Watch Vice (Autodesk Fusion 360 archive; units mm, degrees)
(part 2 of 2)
sketch "Sketch10" plane through (0, 0, -6.85) normal (0, 0, -1) x axis (1, 0, 0)
  curve K1 (-22.3111, 9.6073) -> (-17.5274, -15.6265)
  curve K2 (17.5274, -15.6265) -> (22.3111, 9.6073)
  curve K3 (19.1583, 15.1523) -> (22.3111, 9.6073)
  line L1 (0, 0) -> (-15.2104, 15.1952)
  line L2 (-5, 0) -> (0, 0)
  line L3 (0, 0) -> (-5, 0)
  line L4 (0, 5) -> (0, 0)
  curve K4 (-22.3111, 9.6073) -> (-19.1583, 15.1523)
  curve K5 (19.1583, 15.1523) -> (14.1277, 21.5832)
  curve K6 (-14.1277, 21.5832) -> (-19.1583, 15.1523)
  line L5 (12.1, 21.5832) -> (14.1277, 21.5832)
  line L6 (-14.1277, 21.5832) -> (-12.1, 21.5832)
  curve K7 (10.8585, -21.0162) -> (17.5274, -15.6265)
  curve K8 (-17.5274, -15.6265) -> (-10.8585, -21.0162)
  line L7 (-20.16, -3.95) -> (-19.7081, -3.95)
  line L8 (-20.16, 3.95) -> (-20.16, -3.95)
  line L9 (-19.7081, 3.95) -> (-20.16, 3.95)
  line L10 (-12.1, 21.5832) -> (-12.1, 22.5)
  line L11 (12.1, 22.5) -> (12.1, 21.5832)
  line L12 (-12.1, 21.4183) -> (-12.1, 21.5832)
  line L13 (12.1, 21.4183) -> (12.1, 21.5832)
  line L14 (-12.1, 21.5832) -> (-12.1, 21.4183)
  line L15 (12.1, 21.5832) -> (12.1, 21.4183)
  arc A1 centre (0, 0) radius 20.1 clockwise from (0.8, -20.0841) to (-0.8, -20.0841)
  circle C1 centre (0, 0) radius 21.6
  circle C2 centre (-15.2104, 15.1952) radius 0.625
  arc A2 centre (-14.0183, 18.4859) radius 1.6 clockwise from (-13.0515, 17.211) to (-14.5633, 16.9815)
  arc A3 centre (-15.2104, 15.1952) radius 1.9 clockwise from (-16.9962, 14.5462) to (-14.5633, 16.9815)
  arc A4 centre (-18.5, 13.9997) radius 1.6 clockwise from (-16.9962, 14.5462) to (-17.2241, 13.0342)
  arc A5 centre (14.0183, 18.4859) radius 1.6 clockwise from (14.5633, 16.9815) to (13.0515, 17.211)
  arc A6 centre (15.2104, 15.1952) radius 1.9 clockwise from (14.5633, 16.9815) to (16.9962, 14.5462)
  circle C3 centre (15.2104, 15.1952) radius 0.625
  arc A7 centre (18.5, 13.9997) radius 1.6 clockwise from (17.2241, 13.0342) to (16.9962, 14.5462)
  arc A8 centre (-14.0183, -18.4859) radius 1.6 clockwise from (-14.5633, -16.9815) to (-13.0515, -17.211)
  arc A9 centre (-15.2104, -15.1952) radius 1.9 clockwise from (-14.5633, -16.9815) to (-16.9962, -14.5462)
  arc A10 centre (-18.5, -13.9997) radius 1.6 clockwise from (-17.2241, -13.0342) to (-16.9962, -14.5462)
  circle C4 centre (-15.2104, -15.1952) radius 0.625
  arc A11 centre (15.2104, -15.1952) radius 1.9 clockwise from (16.9962, -14.5462) to (14.5633, -16.9815)
  arc A12 centre (14.0183, -18.4859) radius 1.6 clockwise from (13.0515, -17.211) to (14.5633, -16.9815)
  circle C5 centre (15.2104, -15.1952) radius 0.625
  arc A13 centre (18.5, -13.9997) radius 1.6 clockwise from (16.9962, -14.5462) to (17.2241, -13.0342)
  arc A14 centre (2.1023, -18.9913) radius 1.7 clockwise from (3.612, -19.7728) to (0.8, -20.0841)
  arc A15 centre (-2.1023, -18.9913) radius 1.7 clockwise from (-0.8, -20.0841) to (-3.612, -19.7728)
  circle C6 centre (0, 0) radius 21
  circle C7 centre (0, 0) radius 20.5
  arc A16 centre (0, 0) radius 20.1 clockwise from (-3.612, -19.7728) to (-19.7081, -3.95)
  arc A17 centre (0, 0) radius 20.1 clockwise from (-19.7081, 3.95) to (3.612, -19.7728)
  closed curve K9 centre (-9.882, 22.5)
  closed curve K10 centre (-9.882, -23)
  arc A18 centre (0, -0.5) radius 22.3908 clockwise from (8.6949, -21.1337) to (-8.6949, -21.1337)
  closed curve K11 centre (9.882, -23)
  closed curve K12 centre (9.882, 22.5)
  arc A19 centre (0, 0) radius 22.3908 clockwise from (-8.6949, 20.6337) to (8.6949, 20.6337)
  point P17 (0, 0)
  point P18 (-5, 0)
  point P19 (0, 5)
  point P15 (-15.2104, 15.1952)
  point P16 (0, 0)
  dimension "d108" distance A1 C1 = 1.5
  dimension "d109" diameter C2 = 1.25
  dimension "d110" radius A3 = 1.9
  dimension "d112" radius A2 = 1.6
  dimension "d113" distance P17 P18 = 5
  dimension "d114" distance P17 P19 = 5
  dimension "d120" distance P15 P16 = 21.5
  dimension "d330" = 0.5
  dimension "d331" diameter C6 = 42
extrude "Extrude15" cut sketch "Sketch10" profile of A1 C1 C2 A2 A3 A4 A5 A6 C3 A7 A8 A9 A10 C4 A11 A12 C5 A13 against normal blind 1
extrude "Extrude16" cut sketch "Sketch10" profile of C1 C2 C3 C4 C5 against normal blind 4
sketch "Sketch11" plane through (0, 0, 4.15) normal (0, 0, 1) x axis (-1, 0, 0)
  curve K1 (19.4592, -12.045) -> (0, -22.01)
  curve K2 (0, 22) -> (19.4592, -12.045)
  curve K3 (-19.4592, -12.045) -> (0, 22)
  curve K4 (0, -22.01) -> (-19.4592, -12.045)
  circle C1 centre (0, 0) radius 19
  circle C2 centre (0, 0) radius 20.05
  circle C3 centre (0, 0) radius 20.7
  dimension "d125" diameter C2 = 40.1
  dimension "d423" diameter C3 = 41.4 (= "40 mm + 0.7 * 2 mm")
extrude "Extrude17" cut sketch "Sketch11" profile of C1 C2 against normal blind 1.3
extrude "Extrude37" sketch "Sketch11" profile of C2 C3 blind 0.75 from offset 0.05
extrude "Extrude18" cut of existing geometry no distance stored
work_plane "WorkPlane3"
sketch "Sketch12" plane through (0, 0, -1.75) normal (0, 0, 1) x axis (-1, 0, 0)
  line L1 (-24.1674, 0.75) -> (-20.086, 0.75)
  curve K1 (-24.1674, 0.75) -> (-24.2538, -0.75)
  line L2 (-20.086, -0.75) -> (-24.2538, -0.75)
  line L3 (-22.75, -10) -> (-22.75, 10)
  line L4 (0, 0) -> (-22.75, 0)
  line L5 (-32.75, -10) -> (-22.75, -10)
  line L6 (-32.75, 10) -> (-32.75, -10)
  line L7 (-22.75, 10) -> (-32.75, 10)
  line L8 (-20.8112, 5) -> (-20.8112, -5)
  line L9 (-10.8112, -5) -> (-20.8112, -5)
  line L10 (-10.8112, 5) -> (-10.8112, -5)
  line L11 (-20.8112, 5) -> (-10.8112, 5)
  line L12 (-22.9169, -7.75) -> (-32.75, -7.75)
  line L13 (-22.9169, 7.75) -> (-32.75, 7.75)
  line L14 (-27.8334, -10) -> (-27.8334, -7.75)
  line L15 (-27.8334, 10) -> (-27.8334, 7.75)
  arc A1 centre (0, 0) radius 20.1 clockwise from (-20.086, -0.75) to (-20.086, 0.75)
  arc A2 centre (96.8326, 0) radius 120 clockwise from (-22.75, -10) to (-22.75, 10)
  arc A3 centre (96.8326, 0) radius 117.75 clockwise from (-20.8112, -5) to (-20.8112, 5)
  arc A4 centre (0, 0) radius 20.1 clockwise from (19.7081, -3.95) to (3.612, -19.7728)
  arc A5 centre (0, 0) radius 20.1 clockwise from (-3.612, -19.7728) to (19.7081, 3.95)
  arc A6 centre (0, 0) radius 20.1 clockwise from (-3.612, -19.7728) to (3.612, -19.7728)
  point P10 (-22.75, 0)
  point P11 (0, 0)
  point P7 (-22.75, -10)
  point P8 (-22.75, 10)
  point P12 (-32.75, -10)
  point P14 (-20.8112, -5)
  point P15 (-20.8112, 5)
  point P17 (-10.8112, -5)
  dimension "d129" radius A2 = 120
  dimension "d130" distance P10 P11 = 22.75
  dimension "d131" distance P7 P8 = 20
  dimension "d132" distance P7 P12 = 10
  dimension "d147" distance P14 P15 = 10
  dimension "d148" distance P14 P17 = 10
  dimension "d153" distance A2 A3 = 2.25
  dimension "d232" distance L12 L13 = 15.5 (= "12 mm + 3.5 mm")
extrude "Extrude19" cut sketch "Sketch12" profile of A2 L6 L7 L12 L13 along normal blind 7 and against normal blind 2
fillet "Fillet13" radius 1.6
extrude "Extrude21" cut sketch "Sketch12" profile of A1 L1 L2 A3 L9 L10 L11 blind 2
fillet "Fillet31" radius 1.7
work_plane "WorkPlane4" AlongDistance 23.124
sketch "Sketch13" plane through (23.124, 0, 0) normal (1, 0, 0) x axis (0, 1, 0)
  line L1 (-3.6, -3.05) -> (-3.6, -0.45)
  line L2 (3.6, -3.05) -> (-3.6, -3.05)
  line L3 (3.6, -0.45) -> (3.6, -3.05)
  line L4 (-3.6, -0.45) -> (3.6, -0.45)
  line L5 (0.75, -1.45) -> (-0.75, -1.45)
  line L6 (-0.75, -2.05) -> (-0.75, -1.45)
  line L7 (-0.75, -1.75) -> (-3.6, -1.75)
  line L8 (0.75, -1.45) -> (0.75, -2.05)
  dimension "d138" distance L4 L5 = 1
  dimension "d139" distance L1 L6 = 2.85
  dimension "d140" distance L3 L8 = 2.85 (= "d139")
  dimension "d247" = 6.5
extrude "Extrude20" cut sketch "Sketch13" profile of L1 L2 L3 L4 along normal blind 1 and against normal blind 10
fillet "Fillet14" radius 0.75
delete_face "DeleteFace9"
fillet "Fillet32" radius 0.5
sketch "Sketch26"
  line L1 (-28.6909, 32.7863) -> (28.6626, 32.7863)
  line L2 (-28.6909, -32.2863) -> (-28.6909, 32.7863)
  line L3 (28.6626, -32.2863) -> (-28.6909, -32.2863)
  line L4 (28.6626, 32.7863) -> (28.6626, -32.2863)
  curve K1 (22.3111, -9.6073) -> (24.2921, 5.9411)
  line L5 (24.6626, -7.9065) -> (24.6626, 0.4411)
  curve K2 (-19.5699, 15.0454) -> (-22.3111, -9.6073)
  line L6 (-24.6909, 1.8927) -> (-24.6909, -8.4539)
  point P6 (12.1, 28.7863)
  point P7 (24.2921, 5.9411)
  point P9 (24.6626, 0.4411)
  point P11 (-22.3111, -9.6073)
  point P14 (-24.6909, 1.8927)
  point P15 (12.1, -28.2863)
  dimension "d417" distance L1 P6 = 4
  dimension "d418" distance P7 P9 = 5.5
  dimension "d419" distance L4 L5 = 4
  dimension "d420" distance P11 P14 = 11.5
  dimension "d421" distance L2 L6 = 4
  dimension "d422" distance L3 P15 = 4
component_insert "Component Insert"
mesh "Mesh5"
named bodies: "WatchBlank", "WatchCase", "Lug3", "Lug1", "Lug2", "Lug4"

design "Watch Vice Fixture CAD"
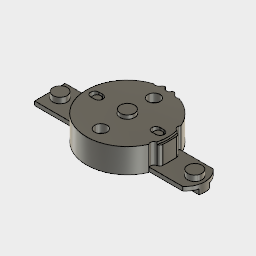
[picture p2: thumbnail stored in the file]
parameter "d90" = 4
parameter "d106" = 4
sketch "Sketch1"
  line L1 (0, 20.2285) -> (0, 20.1)
  line L2 (0, 20.95) -> (0, 20.2285)
  arc A1 centre (0, 0) radius 20.1 clockwise from (19.4682, -5) to (-3.612, 19.7728)
  arc A2 centre (19.1697, -3.3264) radius 1.7 clockwise from (20.869, -3.3751) to (19.4682, -5)
  arc A3 centre (-96.8326, 0) radius 117.75 clockwise from (20.869, 3.3751) to (20.869, -3.3751)
  arc A4 centre (19.1697, 3.3264) radius 1.7 clockwise from (19.4682, 5) to (20.869, 3.3751)
  arc A5 centre (0, 0) radius 20.1 clockwise from (3.612, 19.7728) to (19.4682, 5)
  arc A6 centre (2.1023, 18.9913) radius 1.7 clockwise from (0.8, 20.0841) to (3.612, 19.7728)
  arc A7 centre (0, 0) radius 20.1 clockwise from (-0.8, 20.0841) to (0.8, 20.0841)
  arc A8 centre (-2.1023, 18.9913) radius 1.7 clockwise from (-3.612, 19.7728) to (-0.8, 20.0841)
  arc A9 centre (0, 0) radius 21.6 clockwise from (-17.2241, -13.0342) to (-17.2241, 13.0342)
  arc A10 centre (-18.5, 13.9997) radius 1.6 clockwise from (-16.9962, 14.5462) to (-17.2241, 13.0342)
  arc A11 centre (-15.2104, 15.1952) radius 1.9 clockwise from (-16.9962, 14.5462) to (-14.5633, 16.9815)
  arc A12 centre (-14.0183, 18.4859) radius 1.6 clockwise from (-13.0515, 17.211) to (-14.5633, 16.9815)
  arc A13 centre (0, 0) radius 21.6 clockwise from (-13.0515, 17.211) to (13.0515, 17.211)
  arc A14 centre (14.0183, 18.4859) radius 1.6 clockwise from (14.5633, 16.9815) to (13.0515, 17.211)
  arc A15 centre (15.2104, 15.1952) radius 1.9 clockwise from (14.5633, 16.9815) to (16.9962, 14.5462)
  arc A16 centre (18.5, 13.9997) radius 1.6 clockwise from (17.2241, 13.0342) to (16.9962, 14.5462)
  arc A17 centre (0, 0) radius 21.6 clockwise from (17.2241, 13.0342) to (17.2241, -13.0342)
  arc A18 centre (18.5, -13.9997) radius 1.6 clockwise from (16.9962, -14.5462) to (17.2241, -13.0342)
  arc A19 centre (15.2104, -15.1952) radius 1.9 clockwise from (16.9962, -14.5462) to (14.5633, -16.9815)
  arc A20 centre (14.0183, -18.4859) radius 1.6 clockwise from (13.0515, -17.211) to (14.5633, -16.9815)
  arc A21 centre (0, 0) radius 21.6 clockwise from (13.0515, -17.211) to (-13.0515, -17.211)
  arc A22 centre (-14.0183, -18.4859) radius 1.6 clockwise from (-14.5633, -16.9815) to (-13.0515, -17.211)
  arc A23 centre (-15.2104, -15.1952) radius 1.9 clockwise from (-14.5633, -16.9815) to (-16.9962, -14.5462)
  arc A24 centre (-18.5, -13.9997) radius 1.6 clockwise from (-17.2241, -13.0342) to (-16.9962, -14.5462)
  circle C1 centre (15.2104, 15.1952) radius 0.625
  circle C2 centre (-15.2104, 15.1952) radius 0.625
  circle C3 centre (15.2104, -15.1952) radius 0.625
  circle C4 centre (-15.2104, -15.1952) radius 0.625
  circle C5 centre (5.1662, 20.5772) radius 1.75
  circle C6 centre (-5.1662, 20.5772) radius 1.75
  circle C7 centre (19.7754, 6.7228) radius 1.75
  circle C8 centre (19.7754, -6.7228) radius 1.75
  circle C9 centre (0, 20.1) radius 0.9
  circle C10 centre (0, 20.95) radius 1.75
  arc A25 centre (0, 0) radius 20.1 clockwise from (19.4682, 5) to (19.4682, -5)
  dimension "d6" diameter C8 = 3.5
  dimension "d7" diameter C9 = 1.8
  dimension "d8" diameter C10 = 3.5
extrude "Extrude1" new body sketch "Sketch1" profile of A1 A2 A3 A4 A5 A6 A7 A8 C5 C6 C7 C8 C10 blind 10
extrude "Extrude2" cut sketch "Sketch1" profile of A6 A7 A8 C10 no distance stored
extrude "Extrude3" sketch "Sketch1" profile of A2 A3 A4 A25 blind -1.1
offset_faces "OffsetFaces1" distance -0.1
sketch "Sketch2" plane through (0, 0, 0) normal (1, 0, 0) x axis (0, 1, 0)
  line L1 (-20, 10) -> (19.1, 10)
  line L2 (0, 3) -> (0, 0)
  line L3 (20, 3) -> (-20, 3)
  line L4 (0, 10) -> (0, 3)
  line L5 (-20, 3) -> (-20, 10)
  line L6 (-16, 6) -> (-16, 10)
  line L7 (-14.55, 6) -> (-16, 6)
  line L8 (-14.55, 3) -> (-14.55, 6)
  line L9 (-11.45, 6) -> (-11.45, 3)
  line L10 (-10, 6) -> (-11.45, 6)
  line L11 (-10, 10) -> (-10, 6)
  line L12 (11.45, 6) -> (11.45, 3)
  line L13 (10, 6) -> (11.45, 6)
  line L14 (10, 10) -> (10, 6)
  line L15 (-11.45, 6) -> (-14.55, 6)
  line L16 (-13, 10) -> (-13, 6)
  line L17 (-13, 3) -> (-13, 6)
  line L18 (13, 10) -> (13, 6)
  line L19 (13, 3) -> (13, 6)
  line L20 (-20, 0) -> (19.0241, 0)
  line L21 (-14.25, 0) -> (-14.25, 3)
  line L22 (-13, 0) -> (-13, 3)
  line L23 (-11.75, 0) -> (-11.75, 3)
  line L24 (-11.75, 3) -> (-14.25, 3)
  line L25 (13, 0) -> (13, 3)
  line L26 (11.75, 0) -> (11.75, 3)
  point P10 (-16, 10)
  point P11 (-16, 6)
  point P1 (0, 0)
  dimension "d19" distance P10 P11 = 4
  dimension "d20" distance L8 L9 = 3.1
  dimension "d22" distance L4 L11 = 10
  dimension "d23" distance L6 L11 = 6
  dimension "d24" distance P1 L3 = 3
  dimension "d27" distance L21 L23 = 2.5
  dimension "d28" distance L7 L20 = 6
revolve "Revolve1" sketch "Sketch2" AlongAngle 360
revolve "Revolve2" sketch "Sketch2" AlongAngle 360
work_plane "WorkPlane1" AlongDistance 3
split "Split1" bodies "Clamp Upper"
sketch "Sketch4" plane through (0, 0, 0) normal (0, 1, 0) x axis (1, 0, 0)
  line L1 (-20, 0) -> (20.8174, 0)
  line L2 (20.8174, 4) -> (20.8174, 0)
  line L3 (-20, 4) -> (20.8174, 4)
  line L4 (-20, 0) -> (-20, 4)
  point P4 (20.8174, 0)
  point P5 (20.8174, 4)
  dimension "d41" distance P4 P5 = 4
extrude "Extrude5" add sketch "Sketch4" distance 5.2
delete_face "DeleteFace1"
sketch "Sketch7" plane through (0, 0, 0) normal (0, 0, -1) x axis (1, 0, 0)
  line L1 (20.7887, 2.6) -> (-19.8303, 2.6)
  line L2 (38, 7.5) -> (-38, 7.5)
  line L3 (38, -7.5) -> (38, 7.5)
  line L4 (-38, -7.5) -> (38, -7.5)
  line L5 (-38, 7.5) -> (-38, -7.5)
  line L6 (-19.8303, -2.6) -> (20.7887, -2.6)
  line L7 (-20, 0) -> (-38, 0)
  line L8 (-34.6144, -7.5) -> (-34.6144, 7.5)
  line L9 (0, 7.5) -> (0, 0)
  line L10 (-38, 2.6) -> (-19.8303, 2.6)
  line L11 (-38, -2.6) -> (-19.8303, -2.6)
  line L12 (38, 2.6) -> (20.7887, 2.6)
  line L13 (40.3124, -2.6) -> (20.7887, -2.6)
  arc A1 centre (-96.8326, 0) radius 117.65 clockwise from (20.7691, 3.3723) to (20.7887, 2.6)
  arc A2 centre (19.1697, 3.3264) radius 1.6 clockwise from (19.4506, 4.9016) to (20.7691, 3.3723)
  arc A3 centre (19.7754, 6.7228) radius 1.85 clockwise from (19.4506, 4.9016) to (18.365, 7.92)
  arc A4 centre (0, 0) radius 20 clockwise from (-19.8303, 2.6) to (18.365, 7.92)
  circle C1 centre (0, 13) radius 1.25
  arc A5 centre (0, 0) radius 20 clockwise from (-19.8303, -2.6) to (-19.8303, 2.6)
  circle C2 centre (-33, 0) radius 2.025
  arc A6 centre (-28, 0) radius 10 clockwise from (-34.6144, -7.5) to (-34.6144, 7.5)
  arc A7 centre (28, 0) radius 10 clockwise from (34.6144, 7.5) to (34.6144, -7.5)
  circle C3 centre (33, 0) radius 2.025
  arc A8 centre (5.1662, -20.5772) radius 1.85 clockwise from (3.5232, -19.7268) to (6.1713, -19.0241)
  arc A9 centre (0, 0) radius 20 clockwise from (18.365, -7.92) to (6.1713, -19.0241)
  arc A10 centre (19.7754, -6.7228) radius 1.85 clockwise from (18.365, -7.92) to (19.4506, -4.9016)
  arc A11 centre (19.1697, -3.3264) radius 1.6 clockwise from (20.7691, -3.3723) to (19.4506, -4.9016)
  arc A12 centre (-96.8326, 0) radius 117.65 clockwise from (20.7691, 3.3723) to (20.7691, -3.3723)
  arc A13 centre (19.1697, 3.3264) radius 1.6 clockwise from (19.4506, 4.9016) to (20.7691, 3.3723)
  arc A14 centre (19.7754, 6.7228) radius 1.85 clockwise from (19.4506, 4.9016) to (18.365, 7.92)
  arc A15 centre (0, 0) radius 20 clockwise from (-6.1713, -19.0241) to (18.365, 7.92)
  arc A16 centre (-5.1662, -20.5772) radius 1.85 clockwise from (-6.1713, -19.0241) to (-3.5232, -19.7268)
  arc A17 centre (-2.1023, -18.9913) radius 1.6 clockwise from (-1.8093, -20.5643) to (-3.5232, -19.7268)
  arc A18 centre (0, -20.95) radius 1.85 clockwise from (-1.8093, -20.5643) to (1.8093, -20.5643)
  arc A19 centre (2.1023, -18.9913) radius 1.6 clockwise from (3.5232, -19.7268) to (1.8093, -20.5643)
  circle C4 centre (0, 13) radius 1.55
  circle C5 centre (0, -13) radius 1.55
  point P12 (-38, 7.5)
  point P15 (-38, -7.5)
  point P1 (0, 0)
  point P23 (-33, 0)
  dimension "d73" distance P12 P15 = 15
  dimension "d74" distance P1 P23 = 33
  dimension "d76" radius A6 = 10
  dimension "d77" distance L5 P23 = 5
  dimension "d78" diameter C2 = 4.05
extrude "Extrude14" add sketch "Sketch7" profile of L1 A1 A2 A3 A4 L2 L4 L5 L6 A5 C2 A6 A7 C3 L10 L11 L12 L13 A8 A9 A10 A11 A12 A13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 along normal blind 2
offset_faces "OffsetFaces3" distance 2
extrude "Extrude15" add sketch "Sketch7" profile of L1 L6 A5 C2 A6 A7 C3 L10 L11 L12 L13 A12 A15 along normal blind 4.5
sketch "Sketch3" plane through (0, 0, 0) normal (0, 1, 0) x axis (1, 0, 0)
  line L1 (20, -10) -> (-20, -10)
  line L2 (0, -7) -> (0, 0)
  line L3 (3.6, -9) -> (3.6, -10)
  line L4 (2.1, -9) -> (3.6, -9)
  line L5 (2.1, -7) -> (2.1, -9)
  line L6 (0, -7) -> (2.1, -7)
  line L7 (0, -10) -> (0, -7)
  line L8 (3.6, -10) -> (0, -10)
  line L9 (20.8174, -3) -> (-20, -3)
  line L10 (-22, -7) -> (22, -7)
  line L11 (-22, -1.4022) -> (-22, -7)
  line L12 (22, -1.4022) -> (-22, -1.4022)
  line L13 (22, -7) -> (22, -1.4022)
  point P5 (3.6, -10)
  point P10 (0, -10)
  point P6 (3.6, -9)
  point P7 (2.1, -9)
  point P8 (2.1, -7)
  point P3 (20, -10)
  point P2 (-20, -10)
  dimension "d29" distance L5 L7 = 2.1
  dimension "d30" distance P5 P10 = 3.6
  dimension "d31" distance P5 P6 = 1
  dimension "d32" distance P7 P8 = 2
  dimension "d34" = 1
  dimension "d35" distance P3 L13 = 2
  dimension "d36" distance P2 L11 = 2
revolve "Revolve3" sketch "Sketch3" AlongAngle 360
extrude "Extrude4" cut sketch "Sketch3" profile of L6 L10 L11 L12 L13 distance 10
extrude "Extrude6" new body of existing geometry blind 5.6 bodies "Clamp Jaw 1"
sketch "Sketch5" plane through (0, 0, 0) normal (0, 1, 0) x axis (1, 0, 0)
  line L1 (20.8174, -7.0022) -> (-20, -7.0022)
  line L2 (-20, -1.4022) -> (20.8174, -1.4022)
  line L3 (6.8871, -1.4022) -> (4.8489, -7.0022)
  line L4 (0, -1.4022) -> (0, 0)
  line L5 (0, -7.0022) -> (0, -1.4022)
  line L6 (6.6743, -1.4022) -> (4.636, -7.0022)
  line L7 (0, -6.0022) -> (5, -6.0022)
  line L8 (-6.8871, -1.4022) -> (-4.8489, -7.0022)
  line L9 (-6.6743, -1.4022) -> (-4.636, -7.0022)
  line L10 (0, -6.0022) -> (-5, -6.0022)
  point P13 (5, -6.0022)
  point P14 (0, -6.0022)
  dimension "d47" distance L3 L6 = 0.2
  dimension "d48" angle L2 L6 = 70
  dimension "d49" distance P13 P14 = 5
  dimension "d50" distance L1 L7 = 1
extrude "Extrude7" cut sketch "Sketch5" profile of L1 L2 L3 L5 L6 L7 L8 L9 L10 distance 10 bodies "Clamp Jaw Center", "Clamp Jaws 2"
sketch "Sketch6" plane through (0, 0, 7.0022) normal (0, 0, 1) x axis (-1, 0, 0)
  line L1 (-4.8489, 5) -> (-4.8489, -5)
  line L2 (-19.1013, 5) -> (-4.8489, 5)
  line L3 (-4.8489, -5) -> (-19.1013, -5)
  line L4 (14, -2) -> (16, -2)
  line L5 (16, 2) -> (14, 2)
  line L6 (6.6743, -5) -> (-6.6743, -5)
  line L7 (0, -5) -> (0, 0)
  line L8 (0, 0) -> (14, 0)
  line L9 (16, 0) -> (14, 0)
  line L10 (-14, -2) -> (-16, -2)
  line L11 (-16, 2) -> (-14, 2)
  line L12 (1.7, -4) -> (1.7, -6.1)
  line L13 (-1.7, -4) -> (1.7, -4)
  line L14 (-1.7, -6.1) -> (-1.7, -4)
  line L15 (-1.9, -3.8) -> (1.9, -3.8)
  line L16 (-1.9, -6.1) -> (-1.9, -3.8)
  line L17 (1.9, -3.8) -> (1.9, -6.1)
  line L18 (1.7, 4) -> (1.7, 6.1)
  line L19 (1.9, 3.8) -> (1.9, 6.1)
  line L20 (-1.9, 6.1) -> (-1.9, 3.8)
  line L21 (-1.7, 6.1) -> (-1.7, 4)
  line L22 (-1.7, 4) -> (1.7, 4)
  line L23 (-1.9, 3.8) -> (1.9, 3.8)
  arc A1 centre (-19.1697, 3.3264) radius 1.6 clockwise from (-20.7691, 3.3723) to (-19.4506, 4.9016)
  arc A2 centre (96.8326, 0) radius 117.65 clockwise from (-20.7691, -3.3723) to (-20.7691, 3.3723)
  arc A3 centre (-19.1697, -3.3264) radius 1.6 clockwise from (-19.4506, -4.9016) to (-20.7691, -3.3723)
  arc A4 centre (14, 0) radius 2 clockwise from (14, -2) to (14, 2)
  arc A5 centre (16, 0) radius 2 clockwise from (16, 2) to (16, -2)
  circle C1 centre (15, 0) radius 1.95
  arc A6 centre (-14, 0) radius 2 clockwise from (-14, 2) to (-14, -2)
  arc A7 centre (-16, 0) radius 2 clockwise from (-16, -2) to (-16, 2)
  circle C2 centre (-15, 0) radius 1.95
  circle C3 centre (0, 0) radius 1.75
  arc A8 centre (0, -6.1) radius 1.7 clockwise from (1.7, -6.1) to (-1.7, -6.1)
  arc A9 centre (0, -6.1) radius 1.9 clockwise from (1.9, -6.1) to (-1.9, -6.1)
  arc A10 centre (0, 6.1) radius 1.7 clockwise from (-1.7, 6.1) to (1.7, 6.1)
  arc A11 centre (0, 6.1) radius 1.9 clockwise from (-1.9, 6.1) to (1.9, 6.1)
  arc A12 centre (-19.7754, 6.7228) radius 1.85 clockwise from (-19.1013, 5) to (-19.4506, 4.9016)
  arc A13 centre (-19.7754, -6.7228) radius 1.85 clockwise from (-19.4506, -4.9016) to (-19.1013, -5)
  point P13 (14, -2)
  point P16 (16, -2)
  point P1 (0, 0)
  point P21 (15, 0)
  point P32 (1.7, -6.1)
  dimension "d53" diameter A5 = 4
  dimension "d54" diameter C1 = 3.9 (= "d53 - 0.1 mm")
  dimension "d55" distance P13 P16 = 2
  dimension "d56" distance P1 P21 = 15
  dimension "d61" diameter C3 = 3.5
  dimension "d63" radius A8 = 1.7 (= "( 3.6 / 2 ) * 1 mm - 0.1 mm")
  dimension "d64" distance L6 P32 = 1.1
  dimension "d65" distance L8 L13 = 4
  dimension "d66" = 0.2
extrude "Extrude8" add sketch "Sketch6" profile of C1 C2 along normal blind 2
extrude "Extrude9" cut sketch "Sketch6" profile of A5 A4 L4 L5 C1 A6 L10 A7 C2 L11 along normal blind 7 and against normal blind 1
extrude "Extrude13" cut sketch "Sketch6" profile of C3 no distance stored
extrude "Extrude11" sketch "Sketch6" profile of L6 A8 L12 L14 A10 L18 L21 L22 to an object
extrude "Extrude16" cut sketch "Sketch6" profile of L6 A8 L12 L13 L14 L16 L15 L17 A9 A10 A11 L18 L19 L20 L21 L22 L23 to an object
combine "Combine1" bodies "Clamp Upper", "Clamp Jaw 1", "Clamp Jaw Center", "Clamp Jaws 2"
sketch "Sketch13" plane through (0, 0, 0) normal (0, 0, 1) x axis (-1, 0, 0)
  circle C1 centre (-33, 0) radius 2.025
  circle C2 centre (33, 0) radius 2.025
  circle C3 centre (-33, 0) radius 3.5
  circle C4 centre (33, 0) radius 3.5
  dimension "d133" diameter C3 = 7
extrude "Extrude21" add sketch "Sketch13" along normal blind 2.75
sketch "Sketch14" plane through (0, 0, 9) normal (0, 0, 1) x axis (-1, 0, 0)
  circle C1 centre (0, 0) radius 3.5
  dimension "d136" diameter C1 = 7
extrude "Extrude22" add sketch "Sketch14" along normal blind 2.75
named bodies: "Clamp", "Clamp Upper", "Clamp Jaw 1", "Clamp Jaw Center", "Clamp Jaws 2"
